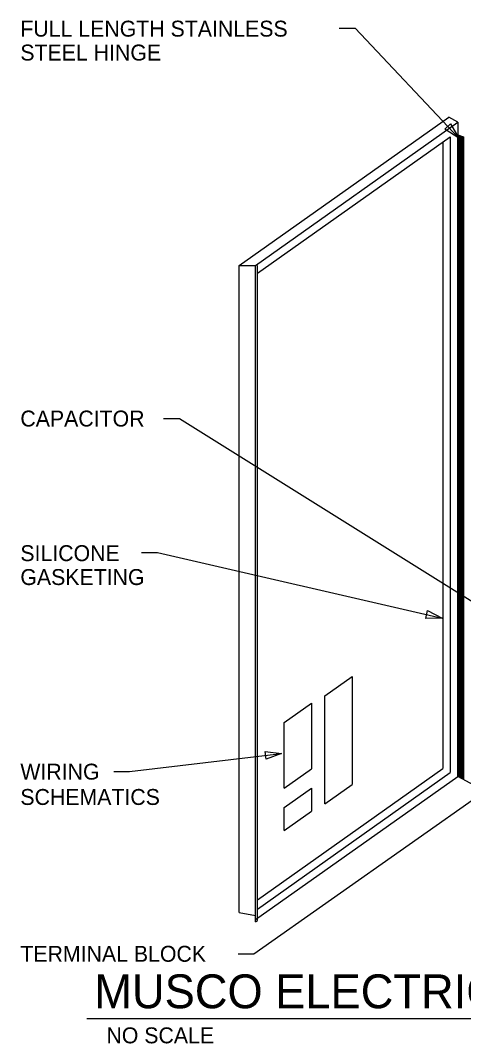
# Model space of a CAD drawing. Extents: x 10314 to 10360.8, y 10093.4 to 10137.8.
# Drawn here: x 10314 to 10332.56, y 10094.69 to 10137.51 of the extents above; entities that cross this region are included whole.
import ezdxf

# ---------------------------------------------------------------- set-up
doc = ezdxf.new("R2010")
doc.units = 0
for name, color, linetype in [('G-ANNO-TEXT', 7, 'Continuous'), ('G-DETL-LINE', 7, 'Continuous'), ('G-DETL-OTLN', 7, 'Continuous')]:
    doc.layers.add(name, color=color, linetype=linetype)

msp = doc.modelspace()

# ---------------------------------------------------------------- linework, layer by layer
at = {"layer": 'G-ANNO-TEXT'}
for p, q in [((10327.356, 10137.185), (10328.022, 10137.185)), ((10328.022, 10137.185), (10332.355, 10132.581)), ((10319.996, 10120.846), (10320.663, 10120.846)), ((10320.663, 10120.846), (10333.396, 10112.898)), ((10319.067, 10115.233), (10319.734, 10115.233)), ((10319.734, 10115.233), (10331.66, 10112.494)), ((10318.573, 10106.067), (10324.937, 10106.829)), ((10323.781, 10098.443), (10335.921, 10106.987)), ((10317.907, 10106.067), (10318.573, 10106.067)), ((10323.114, 10098.443), (10323.781, 10098.443)), ((10316.777, 10095.732), (10358.361, 10095.732))]:
    msp.add_line(p, q, dxfattribs=at)
for points in [[(10332.019, 10133.181), (10332.355, 10132.581), (10331.777, 10132.952)], [(10331.047, 10112.806), (10331.66, 10112.494), (10330.973, 10112.481)], [(10324.255, 10106.915), (10324.937, 10106.829), (10324.295, 10106.585)]]:
    msp.add_lwpolyline(points, close=True, dxfattribs=at)
at = {"layer": 'G-DETL-LINE'}
for p, q in [((10326.752, 10109.244), (10327.896, 10110.053)), ((10327.896, 10110.053), (10327.896, 10105.532)), ((10325.047, 10108.12), (10326.191, 10108.929)), ((10326.191, 10108.929), (10326.191, 10106.191)), ((10326.752, 10104.723), (10326.752, 10109.244)), ((10325.047, 10105.382), (10325.047, 10108.12)), ((10325.047, 10105.382), (10326.191, 10106.191)), ((10326.752, 10104.723), (10327.896, 10105.532)), ((10325.047, 10104.568), (10326.191, 10105.377)), ((10326.191, 10105.377), (10326.191, 10104.407)), ((10325.047, 10103.598), (10325.047, 10104.568)), ((10325.047, 10103.598), (10326.191, 10104.407))]:
    msp.add_line(p, q, dxfattribs=at)
at = {"layer": 'G-DETL-OTLN'}
for p, q in [((10323.167, 10127.253), (10331.947, 10133.462)), ((10332.318, 10133.245), (10331.947, 10133.462)), ((10323.845, 10127.253), (10332.318, 10133.245)), ((10332.318, 10133.245), (10332.318, 10105.87)), ((10332.004, 10132.638), (10332.004, 10106.032)), ((10332.347, 10105.854), (10332.347, 10132.715)), ((10332.377, 10105.837), (10332.377, 10132.704)), ((10332.407, 10105.821), (10332.407, 10132.693)), ((10332.437, 10105.804), (10332.437, 10132.681)), ((10332.467, 10105.787), (10332.467, 10132.67)), ((10332.497, 10105.771), (10332.497, 10132.659)), ((10332.527, 10105.754), (10332.527, 10132.647)), ((10332.557, 10105.738), (10332.557, 10132.636)), ((10323.167, 10127.253), (10323.845, 10127.253)), ((10323.167, 10100.176), (10323.167, 10127.253)), ((10323.845, 10099.782), (10323.845, 10127.253)), ((10323.923, 10099.838), (10323.923, 10127.253)), ((10323.845, 10099.878), (10332.318, 10105.87)), ((10323.923, 10100.318), (10332.004, 10106.032)), ((10341.402, 10100.853), (10332.318, 10105.87)), ((10323.167, 10100.176), (10323.845, 10100.044)), ((10323.845, 10099.782), (10323.923, 10099.838))]:
    msp.add_line(p, q, dxfattribs=at)
for points in [[(10323.923, 10126.924), (10332.004, 10132.638)], [(10331.69, 10132.416), (10331.69, 10106.195)], [(10323.923, 10100.703), (10331.69, 10106.195)]]:
    msp.add_lwpolyline(points, dxfattribs=at)
for points in [[(10332.562, 10132.634), (10332.562, 10105.735), (10332.318, 10105.87), (10332.324, 10132.724)], [(10332.318, 10105.87), (10332.562, 10105.87), (10332.562, 10105.735)]]:
    msp.add_lwpolyline(points, close=True, dxfattribs=at)

# ---------------------------------------------------------------- texts
at = {"layer": 'G-ANNO-TEXT'}
for s, height, p in [('FULL LENGTH STAINLESS', 0.66667, (10313.996, 10136.831)), ('STEEL HINGE', 0.66667, (10313.996, 10135.831)), ('CAPACITOR', 0.6667, (10313.996, 10120.513)), ('SILICONE', 0.6667, (10313.996, 10114.879)), ('GASKETING', 0.6667, (10313.996, 10113.879)), ('WIRING', 0.6667, (10313.996, 10105.734)), ('SCHEMATICS', 0.6667, (10313.996, 10104.674)), ('TERMINAL BLOCK', 0.66667, (10313.996, 10098.11)), ('MUSCO ELECTRICAL ENCLOSURE DETAIL', 1.41667, (10317.094, 10096.165)), ('NO SCALE', 0.6667, (10317.602, 10094.697))]:
    msp.add_text(s, height=height, dxfattribs=at).set_placement(p)

doc.saveas('drawing.dxf')
